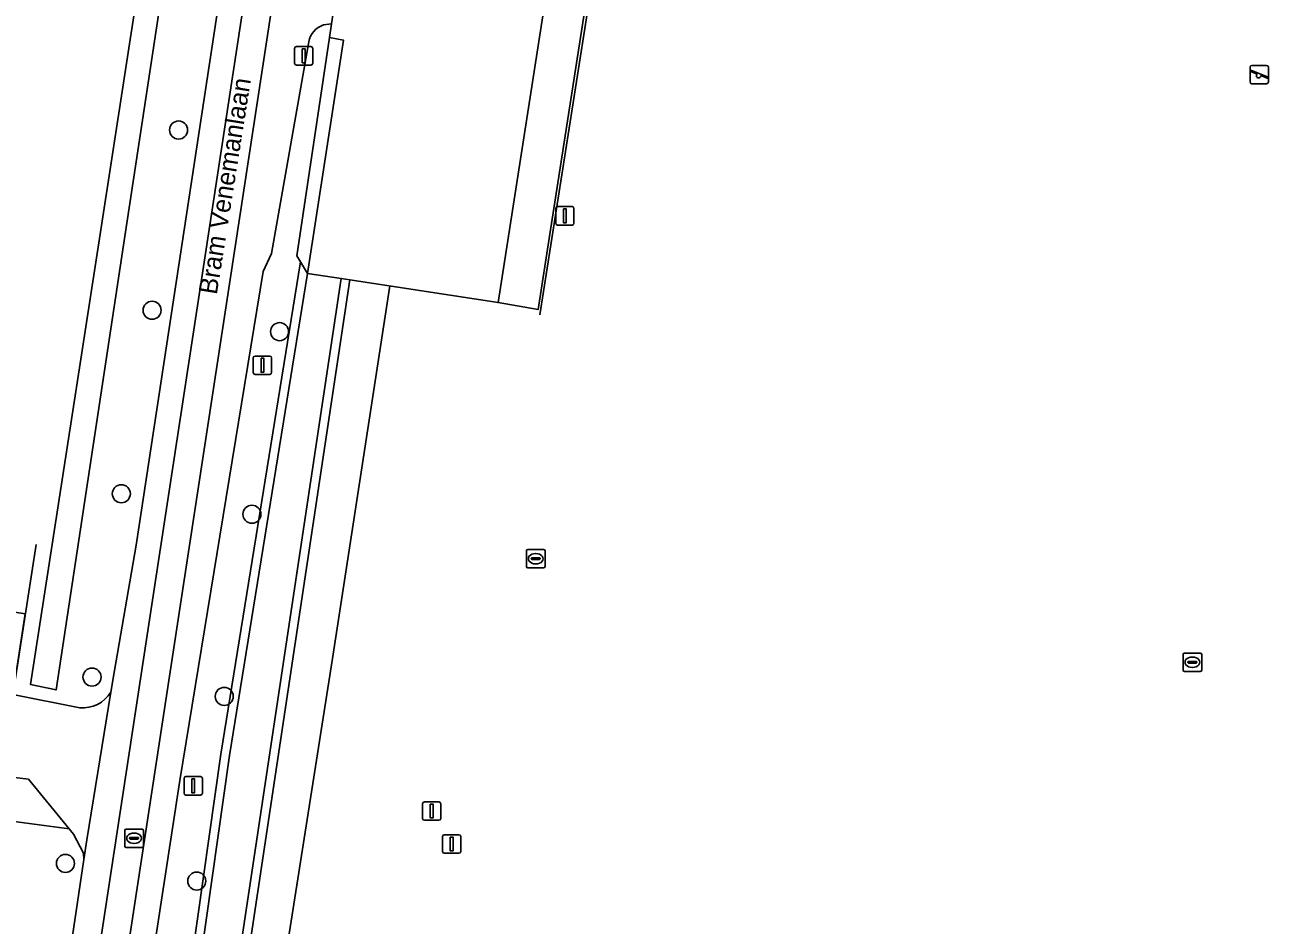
# Model space of a CAD drawing. Extents: x 161090 to 161692, y 379509 to 380907.
# Drawn here: x 161459.2 to 161526.6, y 380212.6 to 380261.3 of the extents above; entities that cross this region are included whole.
import ezdxf

# ---------------------------------------------------------------- set-up
doc = ezdxf.new("R2010")
doc.units = 0
for name, color, linetype in [('IMGEO_Boom', 7, 'Continuous'), ('IMGEO_Greppel_droge_sloot', 7, 'Continuous'), ('IMGEO_Groenvoorziening', 7, 'Continuous'), ('IMGEO_Hek', 7, 'Continuous'), ('IMGEO_Lichtmast', 7, 'Continuous'), ('IMGEO_Oever', 7, 'Continuous'), ('IMGEO_Openbare_ruimte_label', 7, 'Continuous'), ('IMGEO_Pand', 7, 'Continuous'), ('IMGEO_Rijbaan_lokaal_gesloten', 7, 'Continuous'), ('IMGEO_Rijbaan_lokaal_open', 7, 'Continuous'), ('IMGEO_Rioolput', 7, 'Continuous'), ('IMGEO_Speelvoorziening', 7, 'Continuous'), ('IMGEO_Voetpad_gesloten', 7, 'Continuous'), ('IMGEO_Voetpad_open', 7, 'Continuous'), ('IMGEO_Waterleidingput', 7, 'Continuous'), ('IMGEO_Waterloop', 7, 'Continuous')]:
    doc.layers.add(name, color=color, linetype=linetype)

msp = doc.modelspace()

# ---------------------------------------------------------------- linework, layer by layer
at = {"layer": 'IMGEO_Boom'}
for centre in [(161467.497, 380255.64), (161466.065, 380245.889), (161472.961, 380244.732), (161464.403, 380235.963), (161471.464, 380234.855), (161462.817, 380226.049), (161469.968, 380225.004), (161461.382, 380215.969), (161468.483, 380215.013)]:
    msp.add_circle(centre, 0.489, dxfattribs=at)
at = {"layer": 'IMGEO_Greppel_droge_sloot'}
msp.add_lwpolyline([(161469.146, 380279.911), (161467.896, 380280.089), (161463.253, 380250), (161459.495, 380225.647), (161460.876, 380225.356), (161464.612, 380250)], close=True, dxfattribs=at)
at = {"layer": 'IMGEO_Groenvoorziening'}
for points in [[(161468.714, 380289.805), (161473.666, 380289.12), (161475.319, 380300.52), (161477.293, 380313.127), (161481.572, 380340.98), (161476.723, 380344.754), (161468.564, 380345.931), (161467.674, 380339.759), (161468.027, 380339.705), (161454.566, 380250), (161452.226, 380234.4), (161452.191, 380234.169), (161446.05, 380235.084), (161445.627, 380235.147), (161445.404, 380233.707), (161445.183, 380231.716), (161459.211, 380229.466), (161458.539, 380225.11), (161462.153, 380224.392)], [(161463.827, 380225.238), (161464.029, 380226.403), (161465.207, 380233.179), (161472.691, 380282.325), (161467.654, 380283.17), (161468.714, 380289.805)], [(161571.501, 380267.574), (161515.278, 380276.061), (161513.755, 380266.304), (161512.509, 380266.485), (161512.618, 380267.36), (161512.415, 380267.391), (161512.279, 380266.508), (161511.902, 380263.976), (161511.145, 380264.094), (161494.657, 380266.645), (161490.25, 380267.131), (161487.578, 380250), (161486.942, 380245.925), (161484.775, 380246.307), (161476.761, 380247.535), (161466.509, 380179.329)], [(161474.092, 380248.508), (161473.892, 380248.836), (161475.658, 380260.635), (161475.772, 380261.375), (161475.343, 380261.323)], [(161474.536, 380260.41), (161472.522, 380248.965), (161472.065, 380247.978), (161467.572, 380220.455), (161464.514, 380200.592), (161459.926, 380169.997)], [(161460.334, 380169.575), (161462.437, 380169.367), (161462.409, 380169.469), (161462.385, 380169.673), (161462.392, 380169.879), (161462.422, 380170.033), (161463.517, 380177.6), (161469.784, 380221.87), (161474.092, 380248.508)]]:
    msp.add_lwpolyline(points, dxfattribs=at)
for points in [[(161463.253, 380250), (161467.896, 380280.089), (161469.146, 380279.911), (161464.612, 380250), (161460.876, 380225.356), (161459.495, 380225.647)], [(161476.425, 380260.498), (161475.658, 380260.635), (161473.892, 380248.836), (161474.092, 380248.508), (161474.472, 380247.886)], [(161462.38, 380216.189), (161462.364, 380216.53), (161461.823, 380217.553), (161461.582, 380217.846), (161457.51, 380218.386), (161453.402, 380191.532), (161449.794, 380167.944), (161454.229, 380167.285), (161454.417, 380167.98), (161455.256, 380170.608), (161455.869, 380173.505), (161457.01, 380179.886), (161457.863, 380185.825)]]:
    msp.add_lwpolyline(points, close=True, dxfattribs=at)
for centre, radius, start, end in [((161475.716, 380260.18), 1.202, 108.0641, 168.98902), ((161462.329, 380226.123), 1.74, 264.19738, 329.42453)]:
    msp.add_arc(centre, radius, start, end, dxfattribs=at)
at = {"layer": 'IMGEO_Hek'}
for points in [[(161487.042, 380245.645), (161490.407, 380267.114), (161490.951, 380270.588)], [(161558.655, 380153.718), (161472.202, 380166.92), (161467.427, 380173.551), (161469.43, 380186.379), (161475.815, 380227.062), (161478.929, 380247.203)], [(161458.621, 380225.641), (161459.791, 380233.223)]]:
    msp.add_lwpolyline(points, dxfattribs=at)
at = {"layer": 'IMGEO_Lichtmast'}
for p, q in [((161473.769, 380259.251), (161473.769, 380260.051)), ((161473.769, 380260.051), (161473.769, 380259.251)), ((161473.869, 380260.151), (161474.659, 380260.151)), ((161474.659, 380260.151), (161473.869, 380260.151)), ((161474.759, 380260.051), (161474.759, 380259.251)), ((161474.759, 380259.251), (161474.759, 380260.051)), ((161474.659, 380259.151), (161473.869, 380259.151)), ((161473.869, 380259.151), (161474.659, 380259.151)), ((161487.994, 380251.501), (161488.784, 380251.501)), ((161488.784, 380251.501), (161487.994, 380251.501)), ((161487.894, 380250.601), (161487.894, 380251.401)), ((161487.894, 380251.401), (161487.894, 380250.601)), ((161488.884, 380251.401), (161488.884, 380250.601)), ((161488.884, 380250.601), (161488.884, 380251.401)), ((161488.784, 380250.501), (161487.994, 380250.501)), ((161487.994, 380250.501), (161488.784, 380250.501)), ((161471.637, 380243.415), (161472.427, 380243.415)), ((161472.427, 380243.415), (161471.637, 380243.415)), ((161471.537, 380242.515), (161471.537, 380243.315)), ((161471.537, 380243.315), (161471.537, 380242.515)), ((161472.527, 380243.315), (161472.527, 380242.515)), ((161472.527, 380242.515), (161472.527, 380243.315)), ((161472.427, 380242.415), (161471.637, 380242.415)), ((161471.637, 380242.415), (161472.427, 380242.415)), ((161467.795, 380219.769), (161467.795, 380220.569)), ((161467.795, 380220.569), (161467.795, 380219.769)), ((161467.895, 380220.669), (161468.685, 380220.669)), ((161468.685, 380220.669), (161467.895, 380220.669)), ((161468.785, 380220.569), (161468.785, 380219.769)), ((161468.785, 380219.769), (161468.785, 380220.569)), ((161468.685, 380219.669), (161467.895, 380219.669)), ((161467.895, 380219.669), (161468.685, 380219.669)), ((161480.692, 380218.401), (161480.692, 380219.201)), ((161480.692, 380219.201), (161480.692, 380218.401)), ((161480.792, 380219.301), (161481.582, 380219.301)), ((161481.582, 380219.301), (161480.792, 380219.301)), ((161481.682, 380219.201), (161481.682, 380218.401)), ((161481.682, 380218.401), (161481.682, 380219.201)), ((161481.582, 380218.301), (161480.792, 380218.301)), ((161480.792, 380218.301), (161481.582, 380218.301)), ((161481.771, 380216.619), (161481.771, 380217.419)), ((161481.771, 380217.419), (161481.771, 380216.619)), ((161481.871, 380217.519), (161482.661, 380217.519)), ((161482.661, 380217.519), (161481.871, 380217.519)), ((161482.761, 380217.419), (161482.761, 380216.619)), ((161482.761, 380216.619), (161482.761, 380217.419)), ((161482.661, 380216.519), (161481.871, 380216.519)), ((161481.871, 380216.519), (161482.661, 380216.519))]:
    msp.add_line(p, q, dxfattribs=at)
for points in [[(161474.189, 380260.026), (161474.339, 380260.026), (161474.339, 380259.276), (161474.189, 380259.276), (161474.189, 380260.026)], [(161488.314, 380251.376), (161488.464, 380251.376), (161488.464, 380250.626), (161488.314, 380250.626), (161488.314, 380251.376)], [(161471.957, 380243.29), (161472.107, 380243.29), (161472.107, 380242.54), (161471.957, 380242.54), (161471.957, 380243.29)], [(161468.215, 380220.544), (161468.365, 380220.544), (161468.365, 380219.794), (161468.215, 380219.794), (161468.215, 380220.544)], [(161481.112, 380219.176), (161481.262, 380219.176), (161481.262, 380218.426), (161481.112, 380218.426), (161481.112, 380219.176)], [(161482.191, 380217.394), (161482.341, 380217.394), (161482.341, 380216.644), (161482.191, 380216.644), (161482.191, 380217.394)]]:
    msp.add_lwpolyline(points, dxfattribs=at)
for centre, start, end in [((161473.869, 380260.051), 90, 180), ((161473.869, 380260.051), 90, 180), ((161474.659, 380260.051), 0, 90), ((161474.659, 380260.051), 360, 90), ((161473.869, 380259.251), 180, 270), ((161473.869, 380259.251), 180, 270), ((161474.659, 380259.251), 270, 0), ((161474.659, 380259.251), 270, 0), ((161487.994, 380251.401), 90, 180), ((161487.994, 380251.401), 90, 180), ((161488.784, 380251.401), 0, 90), ((161488.784, 380251.401), 360, 90), ((161487.994, 380250.601), 180, 270), ((161487.994, 380250.601), 180, 270), ((161488.784, 380250.601), 270, 0), ((161488.784, 380250.601), 270, 0), ((161471.637, 380243.315), 90, 180), ((161471.637, 380243.315), 90, 180), ((161472.427, 380243.315), 0, 90), ((161472.427, 380243.315), 360, 90), ((161471.637, 380242.515), 180, 270), ((161471.637, 380242.515), 180, 270), ((161472.427, 380242.515), 270, 0), ((161472.427, 380242.515), 270, 0), ((161467.895, 380220.569), 90, 180), ((161467.895, 380220.569), 90, 180), ((161468.685, 380220.569), 0, 90), ((161468.685, 380220.569), 360, 90), ((161467.895, 380219.769), 180, 270), ((161467.895, 380219.769), 180, 270), ((161468.685, 380219.769), 270, 0), ((161468.685, 380219.769), 270, 0), ((161480.792, 380219.201), 90, 180), ((161480.792, 380219.201), 90, 180), ((161481.582, 380219.201), 0, 90), ((161481.582, 380219.201), 360, 90), ((161480.792, 380218.401), 180, 270), ((161480.792, 380218.401), 180, 270), ((161481.582, 380218.401), 270, 0), ((161481.582, 380218.401), 270, 0), ((161481.871, 380217.419), 90, 180), ((161481.871, 380217.419), 90, 180), ((161482.661, 380217.419), 0, 90), ((161482.661, 380217.419), 360, 90), ((161481.871, 380216.619), 180, 270), ((161481.871, 380216.619), 180, 270), ((161482.661, 380216.619), 270, 0), ((161482.661, 380216.619), 270, 0)]:
    msp.add_arc(centre, 0.1, start, end, dxfattribs=at)
at = {"layer": 'IMGEO_Oever'}
for points in [[(161463.988, 380177.533), (161470.255, 380221.799), (161474.472, 380247.886), (161474.092, 380248.508), (161469.784, 380221.87), (161463.517, 380177.6), (161462.422, 380170.033), (161462.392, 380169.879), (161462.385, 380169.673), (161462.409, 380169.469), (161462.437, 380169.367), (161464.156, 380169.197), (161464.399, 380169.214)], [(161465.006, 380169.36), (161465.035, 380169.551), (161465.043, 380169.711), (161466.509, 380179.329), (161476.761, 380247.535), (161476.294, 380247.607), (161466.038, 380179.4), (161464.568, 380169.758)]]:
    msp.add_lwpolyline(points, dxfattribs=at)
at = {"layer": 'IMGEO_Pand'}
msp.add_lwpolyline([(161488.622, 380270.98), (161484.207, 380271.71), (161483.281, 380271.863), (161478.255, 380272.694), (161476.94, 380264.03), (161476.2, 380264.154), (161476.066, 380263.282), (161475.772, 380261.375), (161475.658, 380260.635), (161476.425, 380260.498), (161474.472, 380247.886), (161476.294, 380247.607), (161476.761, 380247.535), (161484.775, 380246.307)], close=True, dxfattribs=at)
at = {"layer": 'IMGEO_Rijbaan_lokaal_gesloten'}
for points in [[(161456.074, 380164.596), (161466.094, 380230.202), (161483.979, 380347.225)], [(161485.505, 380347.041), (161467.599, 380229.99), (161457.567, 380164.364)], [(161477.293, 380313.127), (161475.319, 380300.52), (161473.666, 380289.12), (161473.656, 380289.049), (161472.695, 380282.352), (161472.691, 380282.325), (161465.207, 380233.179), (161464.029, 380226.403), (161463.827, 380225.238), (161462.538, 380217.249), (161462.38, 380216.189), (161457.863, 380185.825)], [(161459.926, 380169.997), (161464.514, 380200.592), (161467.572, 380220.455), (161472.065, 380247.978), (161472.522, 380248.965), (161474.536, 380260.41)]]:
    msp.add_lwpolyline(points, dxfattribs=at)
msp.add_arc((161475.716, 380260.18), 1.202, 108.0641, 168.98902, dxfattribs=at)
at = {"layer": 'IMGEO_Rijbaan_lokaal_open'}
msp.add_lwpolyline([(161496.967, 380422.687), (161497.303, 380424.898), (161498.535, 380426.719), (161500.797, 380441.248), (161501.473, 380445.586), (161499.017, 380445.989), (161498.373, 380441.757), (161495.524, 380423.042), (161485.861, 380359.57), (161485.809, 380359.378), (161483.979, 380347.225), (161466.094, 380230.202), (161456.074, 380164.596), (161457.567, 380164.364), (161467.599, 380229.99), (161485.505, 380347.041), (161487.307, 380359.083), (161487.325, 380359.344)], close=True, dxfattribs=at)
at = {"layer": 'IMGEO_Rioolput'}
for p, q in [((161464.594, 380216.903), (161464.594, 380217.755)), ((161464.669, 380217.829), (161465.521, 380217.829)), ((161465.595, 380217.755), (161465.595, 380216.903)), ((161464.853, 380217.323), (161464.853, 380217.335)), ((161465.291, 380217.286), (161464.893, 380217.286)), ((161464.896, 380217.372), (161465.294, 380217.372)), ((161465.105, 380217.049), (161465.08, 380217.049)), ((161465.082, 380217.609), (161465.107, 380217.609)), ((161465.337, 380217.335), (161465.337, 380217.323)), ((161465.521, 380216.829), (161464.669, 380216.829))]:
    msp.add_line(p, q, dxfattribs=at)
for points in [[(161464.594, 380216.903), (161464.594, 380217.755)], [(161464.669, 380217.829), (161465.521, 380217.829)], [(161465.595, 380217.755), (161465.595, 380216.903)], [(161465.521, 380216.829), (161464.669, 380216.829)]]:
    msp.add_lwpolyline(points, dxfattribs=at)
for centre, radius, start, end in [((161464.671, 380217.753), 0.0765, 91.55205, 178.44795), ((161464.671, 380217.753), 0.0765, 91.55205, 178.44795), ((161465.519, 380217.753), 0.0765, 1.55205, 88.44795), ((161465.519, 380217.753), 0.0765, 1.55205, 88.44795), ((161464.893, 380217.332), 0.0403, 85.87752, 175.75265), ((161464.89, 380217.322), 0.0366, 178.93798, 274.71019), ((161465.294, 380217.329), 0.043, 264.86636, 352.45326), ((161465.298, 380217.334), 0.0386, 1.73085, 96.63898), ((161464.671, 380216.905), 0.0765, 181.55205, 268.44795), ((161464.671, 380216.905), 0.0765, 181.55205, 268.44795), ((161465.519, 380216.905), 0.0765, 271.55205, 358.44795), ((161465.519, 380216.905), 0.0765, 271.55205, 358.44795)]:
    msp.add_arc(centre, radius, start, end, dxfattribs=at)
for centre, major_axis, ratio, start_param, end_param in [((161465.081, 380217.329), (-0.387, 0.002), 0.722429, 4.712389, 7.853982), ((161465.106, 380217.329), (-0.39, 0.002), 0.717154, 1.570796, 4.712389)]:
    msp.add_ellipse(centre, major_axis=major_axis, ratio=ratio, start_param=start_param, end_param=end_param, dxfattribs=at)
at = {"layer": 'IMGEO_Speelvoorziening'}
for p, q in [((161525.449, 380258.238), (161525.449, 380259.038)), ((161525.449, 380259.038), (161525.449, 380258.238)), ((161525.518, 380258.863), (161526.394, 380258.51)), ((161525.549, 380259.138), (161526.339, 380259.138)), ((161526.339, 380259.138), (161525.549, 380259.138)), ((161526.439, 380259.038), (161526.439, 380258.238)), ((161526.439, 380258.238), (161526.439, 380259.038)), ((161525.832, 380258.666), (161525.493, 380258.803)), ((161526.37, 380258.45), (161526.03, 380258.587)), ((161526.339, 380258.138), (161525.549, 380258.138)), ((161525.549, 380258.138), (161526.339, 380258.138))]:
    msp.add_line(p, q, dxfattribs=at)
for centre, radius, start, end in [((161525.549, 380259.038), 0.1, 90, 180), ((161525.549, 380259.038), 0.1, 90, 180), ((161525.506, 380258.833), 0.0327, 68.07798, 248.07798), ((161526.339, 380259.038), 0.1, 0, 90), ((161526.339, 380259.038), 0.1, 360, 90), ((161525.549, 380258.238), 0.1, 180, 270), ((161525.549, 380258.238), 0.1, 180, 270), ((161525.911, 380258.576), 0.12, 130.99278, 5.16318), ((161526.339, 380258.238), 0.1, 270, 0), ((161526.339, 380258.238), 0.1, 270, 0), ((161526.382, 380258.48), 0.0327, 248.07798, 68.07798)]:
    msp.add_arc(centre, radius, start, end, dxfattribs=at)
at = {"layer": 'IMGEO_Voetpad_gesloten'}
msp.add_lwpolyline([(161458.539, 380225.11), (161459.211, 380229.466), (161445.183, 380231.716)], dxfattribs=at)
at = {"layer": 'IMGEO_Voetpad_open'}
for points in [[(161490.25, 380267.131), (161490.783, 380270.549), (161488.77, 380270.861), (161488.622, 380270.98), (161484.775, 380246.307), (161486.942, 380245.925), (161487.578, 380250)], [(161457.51, 380218.386), (161461.582, 380217.846), (161459.38, 380220.521), (161457.865, 380220.709), (161457.773, 380220.105), (161457.713, 380219.714)]]:
    msp.add_lwpolyline(points, close=True, dxfattribs=at)
msp.add_lwpolyline([(161462.153, 380224.392), (161458.539, 380225.11), (161457.865, 380220.709), (161459.38, 380220.521), (161461.582, 380217.846), (161461.823, 380217.553), (161462.364, 380216.53), (161462.38, 380216.189), (161462.538, 380217.249), (161463.827, 380225.238)], dxfattribs=at)
msp.add_arc((161462.329, 380226.123), 1.74, 264.19738, 329.42453, dxfattribs=at)
at = {"layer": 'IMGEO_Waterleidingput'}
for p, q in [((161486.316, 380232.026), (161486.316, 380232.878)), ((161486.391, 380232.952), (161487.243, 380232.952)), ((161486.804, 380232.732), (161486.829, 380232.732)), ((161487.317, 380232.878), (161487.317, 380232.026)), ((161487.243, 380231.952), (161486.391, 380231.952)), ((161486.575, 380232.446), (161486.575, 380232.458)), ((161487.013, 380232.409), (161486.615, 380232.409)), ((161486.618, 380232.495), (161487.016, 380232.495)), ((161486.827, 380232.172), (161486.802, 380232.172)), ((161487.059, 380232.458), (161487.059, 380232.446)), ((161521.831, 380226.424), (161521.831, 380227.276)), ((161521.906, 380227.35), (161522.758, 380227.35)), ((161522.832, 380227.276), (161522.832, 380226.424)), ((161522.09, 380226.844), (161522.09, 380226.856)), ((161522.528, 380226.807), (161522.13, 380226.807)), ((161522.133, 380226.893), (161522.531, 380226.893)), ((161522.342, 380226.57), (161522.317, 380226.57)), ((161522.319, 380227.13), (161522.344, 380227.13)), ((161522.574, 380226.856), (161522.574, 380226.844)), ((161522.758, 380226.35), (161521.906, 380226.35))]:
    msp.add_line(p, q, dxfattribs=at)
for points in [[(161486.316, 380232.026), (161486.316, 380232.878)], [(161486.391, 380232.952), (161487.243, 380232.952)], [(161487.317, 380232.878), (161487.317, 380232.026)], [(161487.243, 380231.952), (161486.391, 380231.952)], [(161521.831, 380226.424), (161521.831, 380227.276)], [(161521.906, 380227.35), (161522.758, 380227.35)], [(161522.832, 380227.276), (161522.832, 380226.424)], [(161522.758, 380226.35), (161521.906, 380226.35)]]:
    msp.add_lwpolyline(points, dxfattribs=at)
for centre, radius, start, end in [((161486.393, 380232.876), 0.0765, 91.55205, 178.44795), ((161486.393, 380232.876), 0.0765, 91.55205, 178.44795), ((161487.241, 380232.876), 0.0765, 1.55205, 88.44795), ((161487.241, 380232.876), 0.0765, 1.55205, 88.44795), ((161486.393, 380232.028), 0.0765, 181.55205, 268.44795), ((161486.393, 380232.028), 0.0765, 181.55205, 268.44795), ((161486.615, 380232.455), 0.0403, 85.87752, 175.75265), ((161486.612, 380232.445), 0.0366, 178.93798, 274.71019), ((161487.016, 380232.452), 0.043, 264.86636, 352.45326), ((161487.02, 380232.457), 0.0386, 1.73085, 96.63898), ((161487.241, 380232.028), 0.0765, 271.55205, 358.44795), ((161487.241, 380232.028), 0.0765, 271.55205, 358.44795), ((161521.908, 380227.274), 0.0765, 91.55205, 178.44795), ((161521.908, 380227.274), 0.0765, 91.55205, 178.44795), ((161522.756, 380227.274), 0.0765, 1.55205, 88.44795), ((161522.756, 380227.274), 0.0765, 1.55205, 88.44795), ((161522.13, 380226.853), 0.0403, 85.87752, 175.75265), ((161522.127, 380226.843), 0.0366, 178.93798, 274.71019), ((161522.531, 380226.85), 0.043, 264.86636, 352.45326), ((161522.535, 380226.855), 0.0386, 1.73085, 96.63898), ((161521.908, 380226.426), 0.0765, 181.55205, 268.44795), ((161521.908, 380226.426), 0.0765, 181.55205, 268.44795), ((161522.756, 380226.426), 0.0765, 271.55205, 358.44795), ((161522.756, 380226.426), 0.0765, 271.55205, 358.44795)]:
    msp.add_arc(centre, radius, start, end, dxfattribs=at)
for centre, major_axis, ratio, start_param, end_param in [((161486.803, 380232.452), (-0.387, 0.002), 0.722429, 4.712389, 7.853982), ((161486.828, 380232.452), (-0.39, 0.002), 0.717154, 1.570796, 4.712389), ((161522.318, 380226.85), (-0.387, 0.002), 0.722429, 4.712389, 7.853982), ((161522.343, 380226.85), (-0.39, 0.002), 0.717154, 1.570796, 4.712389)]:
    msp.add_ellipse(centre, major_axis=major_axis, ratio=ratio, start_param=start_param, end_param=end_param, dxfattribs=at)
at = {"layer": 'IMGEO_Waterloop'}
for points in [[(161476.294, 380247.607), (161474.472, 380247.886), (161470.255, 380221.799), (161463.988, 380177.533), (161462.892, 380169.953)], [(161464.568, 380169.758), (161466.038, 380179.4), (161476.294, 380247.607)]]:
    msp.add_lwpolyline(points, dxfattribs=at)

# ---------------------------------------------------------------- texts
at = {"layer": 'IMGEO_Openbare_ruimte_label'}
msp.add_text('Bram Venemanlaan', height=1, rotation=80.9708, dxfattribs=at).set_placement((161469.564, 380246.701))

doc.saveas('drawing.dxf')
